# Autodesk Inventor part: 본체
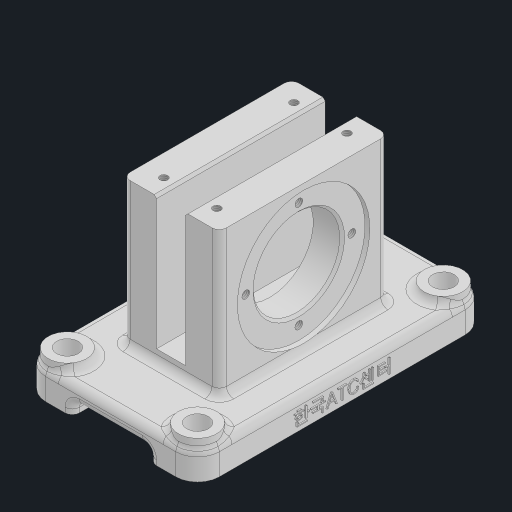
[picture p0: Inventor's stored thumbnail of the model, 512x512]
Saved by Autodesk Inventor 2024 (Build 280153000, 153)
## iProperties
Created: 2025-04
Part Number: 본체
Material: 일반
Document SubType Name: Modeling
Designer: kh_501
Density: 1 g/cm^3
Appearance: 기본값
Author: kh_501
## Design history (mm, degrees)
sketch "스케치1"
  geometry: L1 (36, 60)-(-36, 60); L2 (-36, 60)-(-36, -60); L3 (-36, -60)-(36, -60); L4 (36, -60)-(36, 60); L5 (36, 60)-(-36, -60); L6 (-36, 60)-(36, -60); 1 further point
  constraints: 12 end point, 2 midpoint, 2 parallel, 1 horizontal, 1 perpendicular
  dimensions: "d0" = 120 distance of L3.end L1.start; "d1" = 72 distance of L2.end L3.end
extrude "돌출1" new body sketch "스케치1" distance "d2" = 12; taper "d3" = 0 deg
sketch "스케치2"
  geometry: L1 (72, 35)-(12, 35); L2 (12, 35)-(12, -35); L3 (12, -35)-(72, -35); L4 (72, -35)-(72, 35); L5 (12, 60)-(12, -60) reference; L6 (0, 60)-(0, -60) reference; 2 further points
  constraints: 8 end point, 2 midpoint, 2 parallel, 1 horizontal, 1 perpendicular
  dimensions: "d4" = 70 distance of L3.end L1.start; "d5" = 72 distance between parallel lines of L6 L4
extrude "돌출2" join sketch "스케치2" stored distance "d6" = 40; taper "d7" = 0 deg
sketch "스케치3"
  geometry: L1 (14, 60)-(26, 60); L2 (26, 60)-(26, 5); L3 (26, 5)-(14, 5); L4 (14, 5)-(14, 60); L5 (40, 60)-(0, 60) reference; 3 further points
  constraints: 8 end point, 3 midpoint, 2 parallel, 1 horizontal, 1 perpendicular
  dimensions: "d8" = 12 distance from line of point (26, 32.5) L4; "d9" = 55 distance of L1.end L2.end
extrude "돌출3" cut sketch "스케치3" extent not by distance; stored distance "d10" = 0; taper "d11" = 0 deg
sketch "스케치4"
  geometry: L1 (-60, 0)-(60, 0) reference; C1 r 17 at (0, 42); 2 further points
  constraints: 1 centre point, 1 midpoint, 1 vertical alignment
  dimensions: "d12" = 34 diameter of C1; "d13" = 42 distance from line of C1.centre L1
extrude "돌출4" join sketch "스케치4" distance "d14" = 7; taper "d15" = 0 deg
sketch "스케치5"
  geometry: L1 (20, 72)-(20, 12) reference; L2 (-27, 59)-(-27, 25) reference; L3 (-27, 42)-(20, 42); L4 (20, 69.5)-(18, 69.5); L5 (18, 69.5)-(18, 61); L6 (17, 60)-(6, 60); L7 (6, 72)-(6, 17) reference; L8 (-6, 17)-(-6, 72) reference; L9 (-6, 57)-(-11, 57); L10 (-11, 57)-(-11, 54); L11 (-12, 53)-(-27, 53); L12 (-11, 54)-(-12, 53); L13 (18, 61)-(17, 60); 6 further points
  constraints: 18 end point, 8 point on line, 4 perpendicular, 3 midpoint, 2 horizontal
  dimensions: "d16" = 22 diameter of L11 L3; "d17" = 30 diameter of L9 L3; "d18" = 5 distance of L9.start L9.end; "d19" = 2 distance of L4.start L4.end; "d20" = 36 diameter of L6 L3; "d21" = 55 diameter of point (19, 69.5) L3; "d22" = 1 distance of L10.end point (-11, 53); "d23" = 1 distance of L11.start point (-11, 53) (= d22); "d24" = 1 distance of L5.end point (18, 60) (= d22); "d25" = 1 distance of L6.start point (18, 60) (= d24)
revolve "회전1" sketch "스케치5" stored, may be unused: angle "d26" = 90 deg
sketch "스케치6" dims "d27" = 44
  geometry: L1 (0, 0)-(0, 22); C1 r 27.5 at (0, 0) reference; 2 further points
  constraints: 2 coincident, 2 end point, 1 vertical, 1 vertical alignment, 2 other
hole "구멍1" sketch "스케치6" at (0, 22) diameter "d28" = 3.242; stored, may be unused: countersink angle "d32" = 90 deg, drill point angle "d34" = 118 deg; dims "d29" = 8, "d30" = 4, "d31" = 2, "d33" = 10
sketch "스케치7"
  geometry: L1 (31, 62)-(9, 62); L2 (9, 62)-(9, 8); L3 (9, 8)-(31, 8); L4 (31, 8)-(31, 62); L5 (31, 62)-(9, 8); L6 (9, 62)-(31, 8); 5 further points
  constraints: 12 end point, 4 coincident, 2 midpoint, 2 parallel, 1 horizontal, 1 perpendicular
  dimensions: "d38" = 54 distance of L3.end L1.start; "d39" = 22 distance of L2.end L3.end
hole "구멍2" sketch "스케치7" at (31, 62), (9, 62), (31, 8), (9, 8) diameter "d40" = 3.242; stored, may be unused: countersink angle "d44" = 90 deg, drill point angle "d46" = 118 deg; dims "d41" = 8, "d42" = 4, "d43" = 2, "d45" = 10
node "작업 평면1"
sketch "스케치8"
  geometry: 1 further point
fillet "모깎기1" dims "d48" = 9
chamfer "모따기1" distance "d51" = 1; stored, may be unused: second distance "d52" = 2, angle "d53" = 45 deg
fillet "모깎기4" dims "d54" = 3
sketch "스케치9"
  geometry: L1 (11, 5)-(43, 5); L2 (43, 5)-(43, 0); L3 (43, 0)-(11, 0); L4 (11, 0)-(11, 5); L5 (0, 0)-(54, 0) reference; 2 further points
  constraints: 8 end point, 2 midpoint, 2 parallel, 1 horizontal, 1 perpendicular
  dimensions: "d55" = 32 distance of L2.end L3.end; "d56" = 5 distance of L1.end L2.end
extrude "돌출5" cut sketch "스케치9" extent not by distance; stored distance "d57" = 0; taper "d58" = 0 deg
sketch "스케치10"
  geometry: L1 (27, 51)-(-27, 51); L2 (-27, 51)-(-27, -51); L3 (-27, -51)-(27, -51); L4 (27, -51)-(27, 51); L5 (27, 51)-(-27, -51); L6 (-27, 51)-(27, -51); C1 r 8 at (27, 51); C2 r 8 at (-27, 51); C3 r 8 at (27, -51); C4 r 8 at (-27, -51); C5 r 4.5 at (27, 51); C6 r 4.5 at (-27, 51); C7 r 4.5 at (-27, -51); C8 r 4.5 at (27, -51); 1 further point
  constraints: 12 end point, 8 centre point, 8 coincident, 2 midpoint, 2 parallel, 1 horizontal, 1 perpendicular
  dimensions: "d59" = 102 distance of L3.end L1.start; "d60" = 54 distance of L2.end L3.end; "d61" = 16 diameter of C1; "d62" = 16 diameter of C2; "d63" = 16 diameter of C3; "d64" = 16 diameter of C4; "d71" = 9 diameter of C5; "d72" = 9 diameter of C6; "d73" = 9 diameter of C7; "d74" = 9 diameter of C8
extrude "돌출6" join sketch "스케치10" stored distance "d67" = 10; taper "d68" = 0 deg
fillet "모깎기5" dims "d69" = 3
fillet "모깎기6" dims "d70" = 3
extrude "돌출7" cut sketch "스케치10" extent not by distance; stored distance "d75" = 0; taper "d76" = 0 deg
fillet "모깎기7" dims "d77" = 3
fillet "모깎기8" dims "d78" = 3
fillet "모깎기9" dims "d79" = 3
fillet "모깎기10" dims "d80" = 3
fillet "모깎기11" dims "d81" = 3
sketch "스케치11" dims "d0" = 120, "d1" = 72
  geometry: L1 (0, 0)-(102, 0) reference; 3 further points
  constraints: 1 midpoint, 1 vertical alignment, 1 other
  dimensions: "d82" = 5 distance from line of point (51, 5) L1
feature "엠보싱1" sketch "스케치11" dims "d0" = 120, "d1" = 72, "d83" = 0.5, "d84" = 0
feature "ϓ耀ϕ耀ϗ耀ϙ耀ϛ耀ϝ耀ϟ耀ϡ耀" dims "d0" = 120, "d1" = 72, "d2" = 12, "d3" = 0, "d4" = 70, "d5" = 72, "d6" = 40, "d7" = 0, "d8" = 12, "d9" = 55, "d10" = 0, "d11" = 0, "d12" = 34, "d13" = 42, "d14" = 7, "d15" = 0, "d16" = 22, "d17" = 30, "d18" = 5, "d19" = 2, "d20" = 36, "d21" = 55, "d22" = 1, "d23" = 1 (= d22)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
node "솔리드1"
pattern_circular "원형 패턴1" dims angle "d36" = 360 deg
feature "A9D066F2-1C7D-4E18-AEED-F7BC21143FA4" dims "d28" = 3.242, "d29" = 8, "d30" = 4, "d31" = 2, "d32" = 90 deg, "d33" = 10, "d34" = 118 deg
